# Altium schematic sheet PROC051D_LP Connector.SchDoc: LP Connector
size 431 x 279 mm; Date: Not shown in title block; ApprovedBy: Not shown in title block; CheckedBy: Not shown in title block; Author: Not shown in title block; CompanyName: Not shown in title block; Engineer: Not shown in title block; Organization: Not shown in title block; Address1: Not shown in title block; Address2: Not shown in title block; Address3: Not shown in title block; Address4: Not shown in title block; DocumentNumber: 11; Revision: Use project parameter SCH_Rev; SheetNumber: 11; SheetTotal: 16; PageSetup: Record=PageOptions¦CenterHorizontal=True¦CenterVertical=True¦PrintScale=1.00¦XCorrection=1.00¦YCorrection=1.00¦PrintKind=0¦BorderSize=5000000¦LeftOffset=0¦BottomOffset=0¦Orientation=2¦PaperLength=1000¦PaperWidth=1000¦Scale=100¦PaperSource=15¦PrintQuality=600¦MediaType=1¦DitherType=10¦PaperKind=Letter¦PrintScaleMode=1
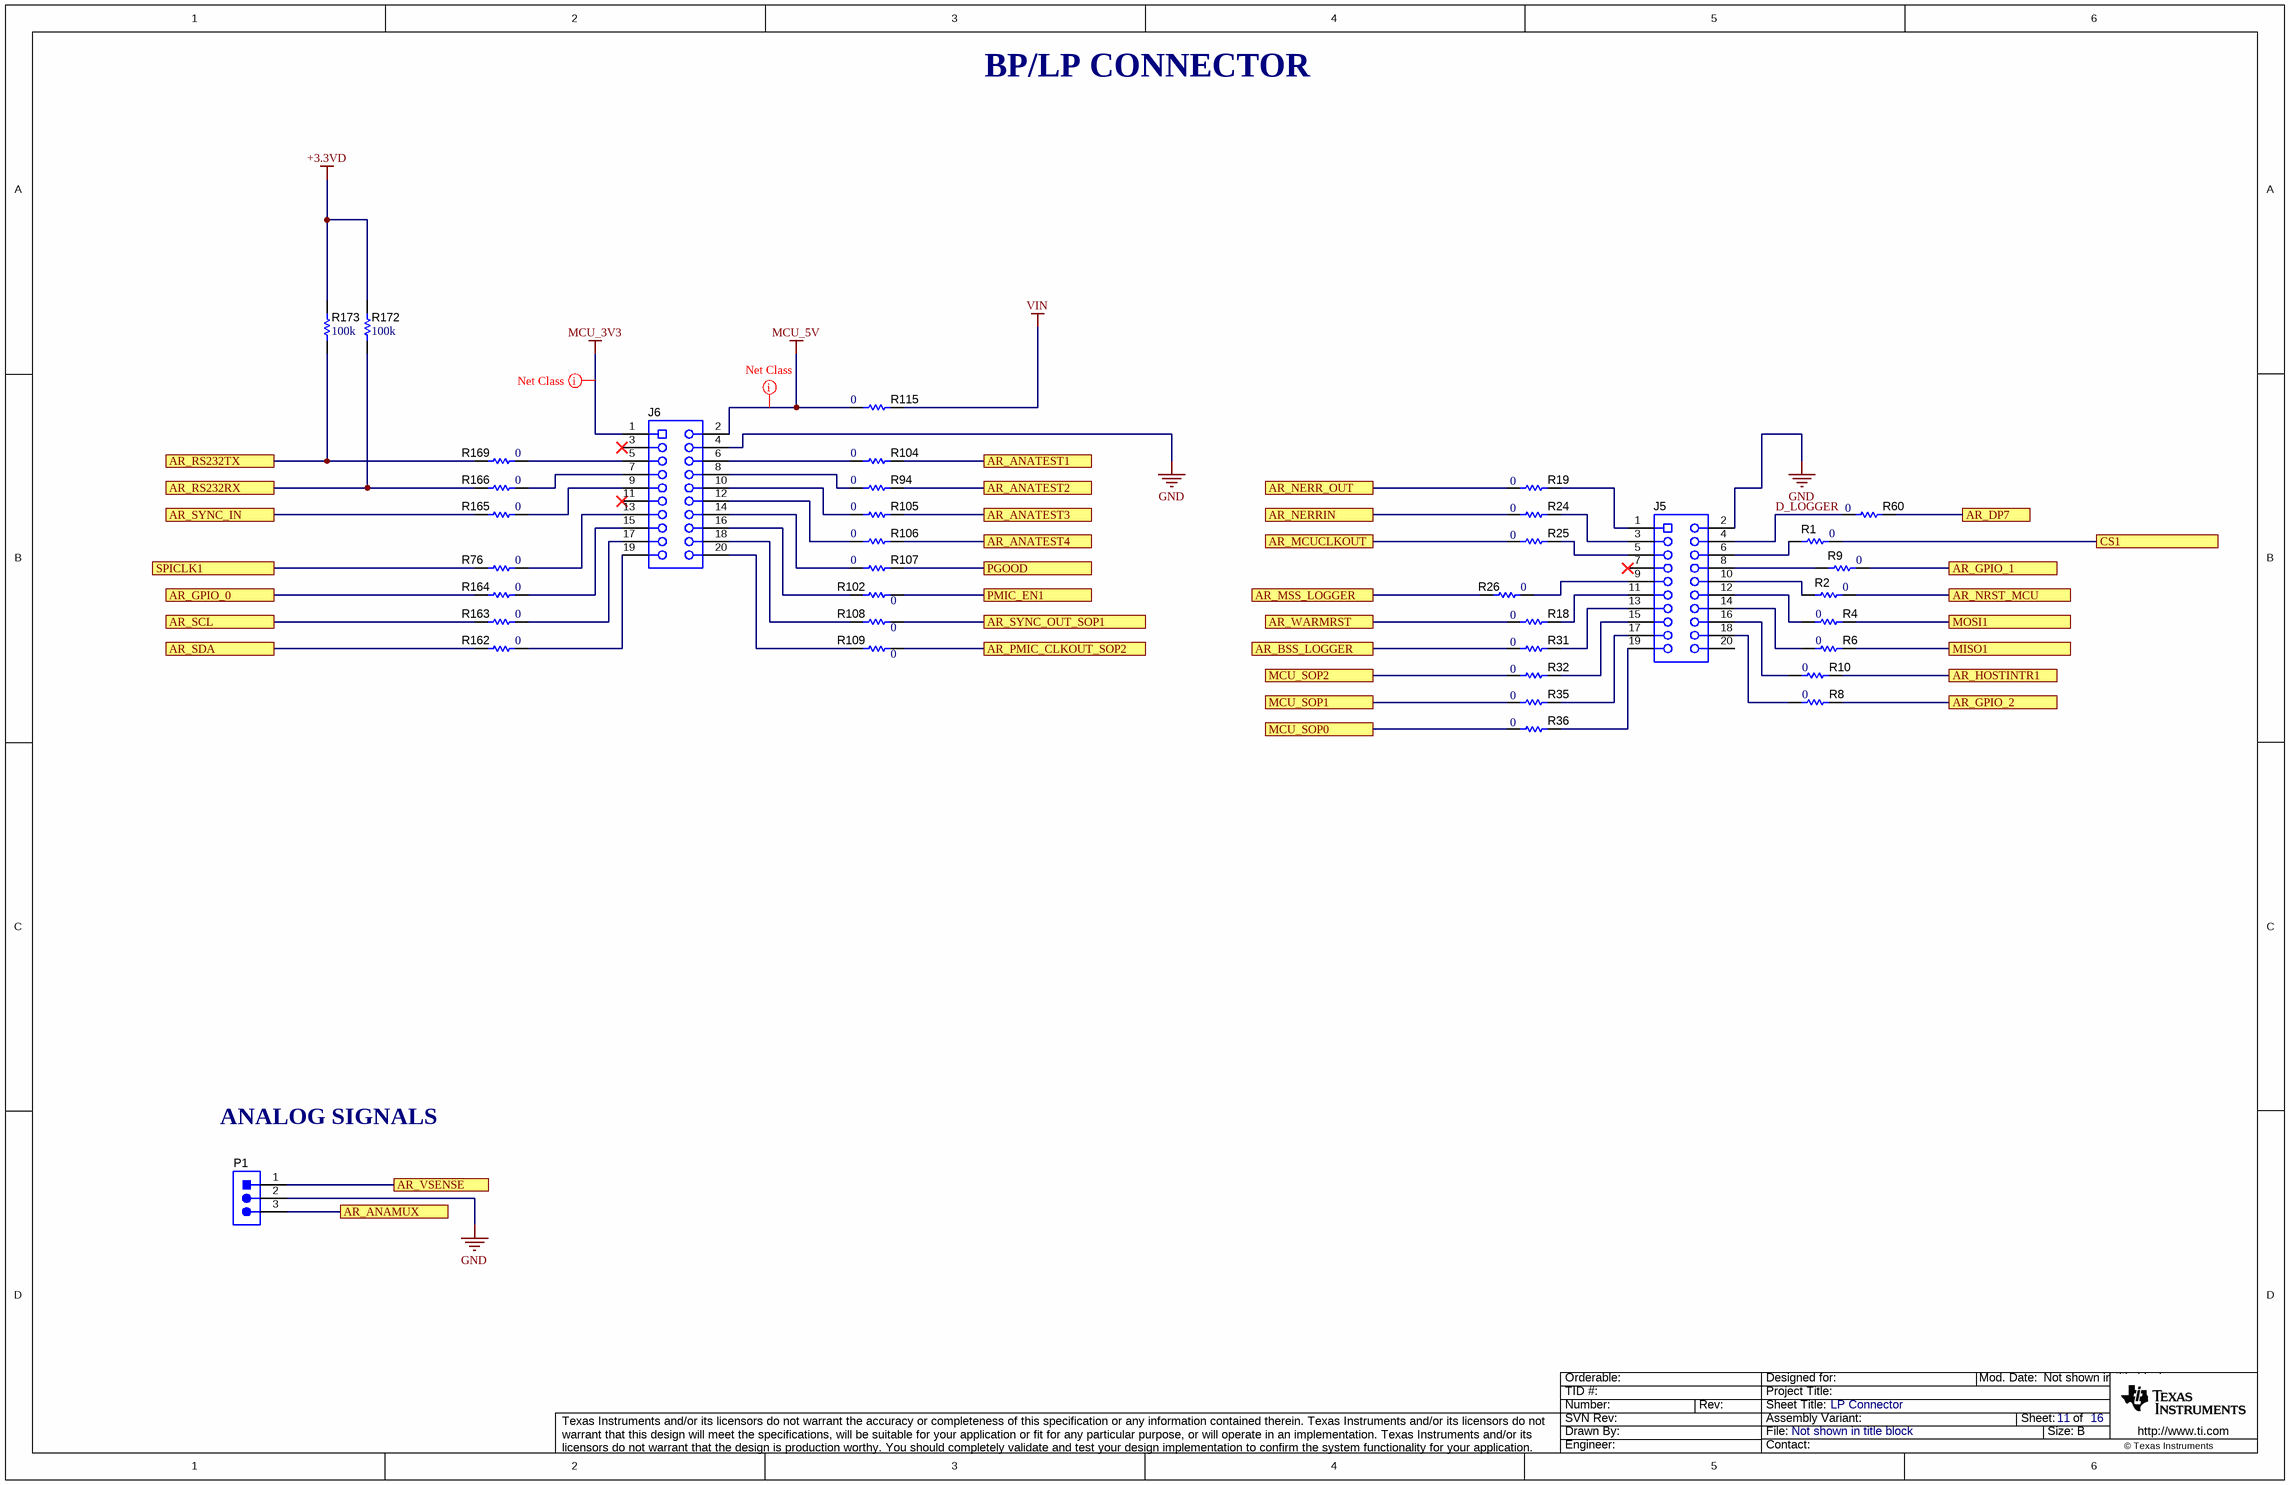
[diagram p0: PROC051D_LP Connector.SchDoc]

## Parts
J5  SSM-110-S-DV  [Samtec_SSM-110-x-DV]  (value not drawn)
J6  SSM-110-S-DV  [Samtec_SSM-110-x-DV]  (value not drawn)
P1  TSW-103-07-T-S  [Samtec_TSW-103-07-T-S]  (value not drawn)
R1  ValueDisplayed: 0  [0201_Silk]  (hidden comment: CRCW02010000Z0ED)
R2  ValueDisplayed: 0  [0201_Silk]  (hidden comment: CRCW02010000Z0ED)
R4  ValueDisplayed: 0  [0201_Silk]  (hidden comment: CRCW02010000Z0ED)
R6  ValueDisplayed: 0  [0201_Silk]  (hidden comment: CRCW02010000Z0ED)
R8  ValueDisplayed: 0  [0201_Silk]  (hidden comment: CRCW02010000Z0ED)
R9  ValueDisplayed: 0  [0201_Silk]  (hidden comment: CRCW02010000Z0ED)
R10  ValueDisplayed: 0  [0201_Silk]  (hidden comment: CRCW02010000Z0ED)
R18  ValueDisplayed: 0  [0201_Silk]  (hidden comment: CRCW02010000Z0ED)
R19  ValueDisplayed: 0  [0201_Silk]  (hidden comment: CRCW02010000Z0ED)
R24  ValueDisplayed: 0  [0201_Silk]  (hidden comment: CRCW02010000Z0ED)
R25  ValueDisplayed: 0  [0201_Silk]  (hidden comment: CRCW02010000Z0ED)
R26  ValueDisplayed: 0  [0201_Silk]  (hidden comment: CRCW02010000Z0ED)
R31  ValueDisplayed: 0  [0201_Silk]  (hidden comment: CRCW02010000Z0ED)
R32  ValueDisplayed: 0  [0201_Silk]  (hidden comment: CRCW02010000Z0ED)
R35  ValueDisplayed: 0  [0201_Silk]  (hidden comment: CRCW02010000Z0ED)
R36  ValueDisplayed: 0  [0201_Silk]  (hidden comment: CRCW02010000Z0ED)
R60  ValueDisplayed: 0  [0201_Silk]  (hidden comment: CRCW02010000Z0ED)
R76  ValueDisplayed: 0  [0201_Silk]  (hidden comment: CRCW02010000Z0ED)
R94  ValueDisplayed: 0  [0201_Silk]  (hidden comment: CRCW02010000Z0ED)
R102  ValueDisplayed: 0  [0201_Silk]  (hidden comment: CRCW02010000Z0ED)
R104  ValueDisplayed: 0  [0201_Silk]  (hidden comment: CRCW02010000Z0ED)
R105  ValueDisplayed: 0  [0201_Silk]  (hidden comment: CRCW02010000Z0ED)
R106  ValueDisplayed: 0  [0201_Silk]  (hidden comment: CRCW02010000Z0ED)
R107  ValueDisplayed: 0  [0402L]  (hidden comment: ERJ-2GE0R00X)
R108  ValueDisplayed: 0  [0201_Silk]  (hidden comment: CRCW02010000Z0ED)
R109  ValueDisplayed: 0  [0201_Silk]  (hidden comment: CRCW02010000Z0ED)
R115  ValueDisplayed: 0  [2010]  (hidden comment: CRCW20100000Z0EF)
R162  ValueDisplayed: 0  [0201_Silk]  (hidden comment: CRCW02010000Z0ED)
R163  ValueDisplayed: 0  [0201_Silk]  (hidden comment: CRCW02010000Z0ED)
R164  ValueDisplayed: 0  [0201_Silk]  (hidden comment: CRCW02010000Z0ED)
R165  ValueDisplayed: 0  [0201_Silk]  (hidden comment: CRCW02010000Z0ED)
R166  ValueDisplayed: 0  [0201_Silk]  (hidden comment: CRCW02010000Z0ED)
R169  ValueDisplayed: 0  [0201_Silk]  (hidden comment: CRCW02010000Z0ED)
R172  ValueDisplayed: 100k  [0402L]  (hidden comment: CRCW0402100KFKED)
R173  ValueDisplayed: 100k  [0402L]  (hidden comment: CRCW0402100KFKED)

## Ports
AR_ANAMUX, AR_ANATEST1, AR_ANATEST2, AR_ANATEST3, AR_ANATEST4, AR_BSS_LOGGER, AR_DP7, AR_GPIO_0, AR_GPIO_1, AR_GPIO_2, AR_HOSTINTR1, AR_MCUCLKOUT, AR_MSS_LOGGER, AR_NERR_OUT, AR_NERRIN, AR_NRST_MCU, AR_PMIC_CLKOUT_SOP2, AR_RS232RX, AR_RS232TX, AR_SCL, AR_SDA, AR_SYNC_IN, AR_SYNC_OUT_SOP1, AR_VSENSE, AR_WARMRST, CS1, MCU_SOP0, MCU_SOP1, MCU_SOP2, MISO1, MOSI1, PGOOD, PMIC_EN1, SPICLK1

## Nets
+3.3VD: R172.2 R173.2
GND: J5.2 J6.4 P1.2
MCU_3V3: J6.1
MCU_5V: J6.2 R115.1
VIN: R115.2
AR_ANAMUX: P1.3 ; port AR_ANAMUX
AR_ANATEST1: R104.2 ; port AR_ANATEST1
AR_ANATEST2: R94.2 ; port AR_ANATEST2
AR_ANATEST3: R105.2 ; port AR_ANATEST3
AR_ANATEST4: R106.2 ; port AR_ANATEST4
AR_BSS_LOGGER: R31.1 ; port AR_BSS_LOGGER
AR_DP7: R60.2 ; port AR_DP7
AR_GPIO_0: R164.1 ; port AR_GPIO_0
AR_GPIO_1: R9.2 ; port AR_GPIO_1
AR_GPIO_2: R8.2 ; port AR_GPIO_2
AR_HOSTINTR1: R10.2 ; port AR_HOSTINTR1
AR_MCUCLKOUT: R25.1 ; port AR_MCUCLKOUT
AR_MSS_LOGGER: R26.1 ; port AR_MSS_LOGGER
AR_NERR_OUT: R19.1 ; port AR_NERR_OUT
AR_NERRIN: R24.1 ; port AR_NERRIN
AR_NRST_MCU: R2.2 ; port AR_NRST_MCU
AR_PMIC_CLKOUT_SOP2: R109.2 ; port AR_PMIC_CLKOUT_SOP2
AR_RS232RX: R166.1 R172.1 ; port AR_RS232RX
AR_RS232TX: R169.1 R173.1 ; port AR_RS232TX
AR_SCL: R163.1 ; port AR_SCL
AR_SDA: R162.1 ; port AR_SDA
AR_SYNC_IN: R165.1 ; port AR_SYNC_IN
AR_SYNC_OUT_SOP1: R108.2 ; port AR_SYNC_OUT_SOP1
AR_VSENSE: P1.1 ; port AR_VSENSE
AR_WARMRST: R18.1 ; port AR_WARMRST
CS1: R1.2 ; port CS1
D_LOGGER: J5.4 R60.1
MCU_SOP0: R36.1 ; port MCU_SOP0
MCU_SOP1: R35.1 ; port MCU_SOP1
MCU_SOP2: R32.1 ; port MCU_SOP2
MISO1: R6.2 ; port MISO1
MOSI1: R4.2 ; port MOSI1
PGOOD: R107.2 ; port PGOOD
PMIC_EN1: R102.2 ; port PMIC_EN1
SPICLK1: R76.1 ; port SPICLK1
NetJ5_1: J5.1 R19.2
NetJ5_3: J5.3 R24.2
NetJ5_5: J5.5 R25.2
NetJ5_6: J5.6 R1.1
NetJ5_8: J5.8 R9.1
NetJ5_9: J5.9 R26.2
NetJ5_10: J5.10 R2.1
NetJ5_11: J5.11 R18.2
NetJ5_12: J5.12 R4.1
NetJ5_13: J5.13 R31.2
NetJ5_14: J5.14 R6.1
NetJ5_15: J5.15 R32.2
NetJ5_16: J5.16 R10.1
NetJ5_17: J5.17 R35.2
NetJ5_18: J5.18 R8.1
NetJ5_19: J5.19 R36.2
NetJ6_5: J6.5 R169.2
NetJ6_6: J6.6 R104.1
NetJ6_7: J6.7 R166.2
NetJ6_8: J6.8 R94.1
NetJ6_9: J6.9 R165.2
NetJ6_10: J6.10 R105.1
NetJ6_12: J6.12 R106.1
NetJ6_13: J6.13 R76.2
NetJ6_14: J6.14 R107.1
NetJ6_15: J6.15 R164.2
NetJ6_16: J6.16 R102.1
NetJ6_17: J6.17 R163.2
NetJ6_18: J6.18 R108.1
NetJ6_19: J6.19 R162.2
NetJ6_20: J6.20 R109.1

Not connected (* = marked no-connect by the designer): J5 7* 20; J6 3* 11*

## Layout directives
net class PWR: MCU_3V3, MCU_5V

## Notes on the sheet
- BP/LP CONNECTOR
- ANALOG SIGNALS

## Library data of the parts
J5 J6 = CMP-0078182-1: Receptacle, 2.54mm, 10x2, Gold with Tin tail, SMT; Manufacturer: Samtec; Pitch_mm: 2.54; Gender: Female; Cert_CSA: Y; Voltage_V: 405V; Current_A: 5.2A; Row_Count: 2; CompType: Socket Strip
P1 = CMP-0075530-2: Header, 2.54 mm, 3x1, Tin, TH; Manufacturer: Samtec; Pitch_mm: 2.54; Cert_VDE: N; Gender: Male; Cert_CSA: Y; Voltage_V: 550V; Green_REACh: Passed; Current_A: 6.3A; Green_Lifecycle: Active; Row_Count: 1
R1 R2 R4 R6 R8-R10 R18 R19 R24-R26 R31 R32 R35 R36 R60 R76 R94 R102 R104-R106 R108 R109 R162-R166 R169 = CMP-0027008-4: RES, 0, 5%, 0.05 W, 0201; Manufacturer: Vishay-Dale; Power_W: 50mW; TempCo: ppm/C; Value_Code: 0000; Value: 0; EIA_Code: E24; SizeX_mm: 0.6; SizeY_mm: 0.3; SizeZ_mm: 0.26; Value2: 0.05W; SizeArea_mm2: 0.18; AEC Qualified: N; AEC Category: Q200
R107 = CMP-0026992-3: RES, 0, 5%, 0.1 W, AEC-Q200 Grade 0, 0402; Manufacturer: Panasonic; Power_W: 100mW; TempCo: 600 ppm/C; Value_Code: 0000; Value: 0; EIA_Code: E24; SizeX_mm: 1; SizeY_mm: 0.5; SizeZ_mm: 0.6; Value2: 0.1W; AEC Qualified: Y; VDC_V: 50V; AEC Category: Q200; SizeAreaWB_mm2: 3
R115 = CMP-0016044-3: RES, 0, 5%, 0.75 W, AEC-Q200 Grade 0, 2010; Manufacturer: Vishay-Dale; Power_W: 750mW; TempCo: ppm/C; Value_Code: 0000; Value: 0; EIA_Code: E24; SizeX_mm: 5; SizeY_mm: 2.5; SizeZ_mm: 1.66; Value2: 0.75W; SizeArea_mm2: 12.5; AEC Qualified: Y; AEC Category: Q200
R172 R173 = CMP-0025950-3: RES, 100 k, 1%, 0.063 W, AEC-Q200 Grade 0, 0402; Manufacturer: Vishay-Dale; Power_W: 63mW; TempCo: 100 ppm/C; Value: 100k; EIA_Code: E96; SizeX_mm: 1; SizeY_mm: 0.5; SizeZ_mm: 0.6; Value2: 0.063W; AEC Qualified: Y; VDC_V: 50V; AEC Category: Q200; AEC Grade: 0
